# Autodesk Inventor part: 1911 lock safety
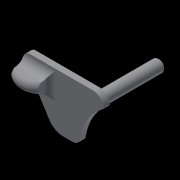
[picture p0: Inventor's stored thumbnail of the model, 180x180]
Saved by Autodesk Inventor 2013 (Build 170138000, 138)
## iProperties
Created: 2013-01
Part Number: 1911 lock safety
Material: Generic
Document SubType Name: Modeling
Designer: John
Density: 1 g/cm^3
Author: John
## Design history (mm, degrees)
sketch "Sketch1"
  geometry: L1 (-20.371, 4.064)-(0.508, 4.064) reference; L2 (-9.449, -13.97)-(-6.18, -13.97); L3 (-13.972, -11.463)-(-17.113, -6.437); L4 (49.396, -38.895)-(105.507, -38.895); L5 (49.396, -38.895)-(67.43, -38.895); L6 (-22.403, 2.032)-(-22.403, -3.052); A1 r 19.05 centre (14.986, -14.986) between (3.712, 0.37) and (-3.822, -11.961) reference; A2 r 2.388 centre (-6.18, -11.582) between (-6.18, -13.97) and (-3.822, -11.961) reference; A3 r 3.556 centre (0.508, 0.508) between (4.012, 1.114) and (0.508, 4.064); A4 r 5.334 centre (-9.449, -8.636) between (-13.972, -11.463) and (-9.449, -13.97) reference; A5 r 5.588 centre (-21.852, -9.398) between (-17.113, -6.437) and (-21.666, -3.813); A6 r 0.762 centre (-21.641, -3.052) between (-22.403, -3.052) and (-21.666, -3.813); A7 r 2.032 centre (-20.371, 2.032) between (-20.371, 4.064) and (-22.403, 2.032); A8 r 0.762 centre (3.261, 0.984) between (3.712, 0.37) and (4.012, 1.114); 2 further points
  constraints: 17 point on circle, 12 end point, 12 tangent, 8 centre point, 2 horizontal, 2 point on line, 6 other
  dimensions: "d18" = 18.034 distance of L4.start L5.end; "d22" = 0.762 radius of A6; "d23" = 2.032 radius of A7; "d24" = 0.762 radius of A8
extrude "Extrusion1" new body sketch "Sketch1" distance "d25" = 1.9812; taper "d26" = 0 deg
sketch "Sketch2"
  geometry: C1 r 1.975 at (0, 0); 1 further point
  constraints: 1 centre point, 1 coincident
  dimensions: "d27" = 3.9497 diameter of C1
extrude "Extrusion2" join sketch "Sketch2" distance "d28" = 20.955; taper "d29" = 0 deg
sketch "Sketch3"
  geometry: L1 (-1.975, -20.955)-(1.975, -20.955) reference; L2 (1.975, 0)-(1.975, -20.955) reference; L3 (-1.975, 0)-(-1.975, -20.955) reference; L4 (0, -20.955)-(0, -2.386); A1 r 2.286 centre (0, -18.669) between (-1.975, -19.82) and (0, -20.955); 1 further point
  constraints: 2 end point, 2 point on circle, 2 point on line, 1 centre point, 1 midpoint, 1 parallel, 1 tangent
revolve "Revolution1" sketch "Sketch3" stored, may be unused: angle "d31" = 90 deg
sketch "Sketch4"
  geometry: L1 (4.775, 3.814)-(7.62, 3.814); L2 (7.62, 3.814)-(7.62, 0.512); L3 (7.62, 0.512)-(4.775, 0.512); L4 (1.981, 6.608)-(1.981, -2.282); A1 r 2.794 centre (4.775, 6.608) between (1.981, 6.608) and (4.775, 3.814); A2 r 2.794 centre (4.775, -2.282) between (4.775, 0.512) and (1.981, -2.282); 3 further points
  constraints: 8 end point, 4 point on circle, 3 tangent, 2 centre point, 2 perpendicular, 2 point on line, 1 equal radius
  dimensions: "d35" = 2.794 radius of A1
extrude "Extrusion3" join sketch "Sketch4" distance "d36" = 10.7696; taper "d37" = 0 deg
sketch "Sketch5"
  geometry: L1 (13.972, -11.463)-(17.113, -6.437) reference; L2 (22.403, -3.052)-(22.403, 2.032) reference; L3 (20.371, 4.064)-(-0.508, 4.064) reference; L4 (18.545, 4.064)-(18.545, 7.341); L5 (18.545, 7.341)-(25.298, 6.663); L6 (25.298, 6.663)-(25.298, -9.398); L7 (25.298, -9.398)-(16.216, -7.872); A1 r 5.588 centre (21.852, -9.398) between (21.666, -3.813) and (17.113, -6.437) reference; A2 r 0.762 centre (21.641, -3.052) between (21.666, -3.813) and (22.403, -3.052) reference; A3 r 2.032 centre (20.371, 2.032) between (22.403, 2.032) and (20.371, 4.064) reference
  constraints: 8 end point, 2 point on line, 1 parallel, 1 perpendicular
extrude "Extrusion4" cut sketch "Sketch5" stored distance "d38" = 8.7376; taper "d39" = 0 deg
sketch "Sketch7"
  geometry: L1 (-2.032, -5.639)-(-2.032, -2.794) reference; L2 (6.706, -4.067)-(6.706, -1.778); L3 (-2.032, -4.067)-(-2.032, 1.981); L4 (20.879, 0)-(8.484, 0); L5 (10.2, 0)-(10.2, -6.82); L6 (10.2, -6.82)-(-2.032, -6.82); L7 (-2.032, -6.82)-(-2.032, -4.067); A1 r 1.778 centre (8.484, -1.778) between (8.484, 0) and (6.706, -1.778); A2 r 6.858 centre (2.337, 1.219) between (-2.032, -4.067) and (6.706, -4.067); 1 further point
  constraints: 12 end point, 4 point on circle, 3 perpendicular, 2 centre point, 2 parallel, 2 tangent, 1 point on line
extrude "Extrusion5" cut sketch "Sketch7" stored distance "d47" = 8.7376; taper "d48" = 0 deg
workplane "Work Plane1"
sketch "Sketch8"
  geometry: L1 (7.62, 3.814)-(6.773, 3.814); L2 (7.62, 0.512)-(6.773, 0.512); L3 (7.781, 3.814)-(7.781, 0.512); L4 (7.62, 3.814)-(7.781, 3.814); L5 (7.62, 0.512)-(7.781, 0.512); A1 r 2.032 centre (5.588, 2.163) between (6.773, 0.512) and (6.773, 3.814); 1 further point
  constraints: 10 end point, 2 parallel, 2 perpendicular, 2 point on circle, 1 centre point
sketch "Sketch9"
  geometry: L1 (4.369, -1.572)-(4.369, 5.286); A1 r 6.858 centre (4.369, 5.286) between (0, 0) and (8.738, 0) reference; A2 r 6.858 centre (4.369, 5.286) between (0, 0) and (8.738, 0); A3 r 6.858 centre (4.369, 5.286) between (-0.927, 0.929) and (9.878, 1.202); 1 further point
  constraints: 6 point on circle, 2 centre point, 2 coincident, 2 end point, 1 vertical
  dimensions: "d51" = 6.858 distance of L1.start L1.end (derived)
sweep "Sweep1" sketch "Sketch8", "Sketch9" dims "d52" = 0
sketch "Sketch11"
  geometry: A1 r 3.442 centre (9.25, -8.702) between (11.467, -6.069) and (5.821, -8.407) reference; A2 r 1.778 centre (9.25, -8.702) between (7.993, -9.959) and (11.028, -8.702); A3 r 8.128 centre (19.156, -8.702) between (11.467, -6.069) and (11.028, -8.702); A4 r 8.128 centre (2.246, -15.706) between (7.993, -9.959) and (5.821, -8.407)
  constraints: 8 point on circle, 3 centre point, 1 tangent
extrude "Extrusion7" cut sketch "Sketch11" stored distance "d63" = 1.7526; taper "d64" = 0 deg
body "Solid1"
other parameters: "d30" = 4.572
